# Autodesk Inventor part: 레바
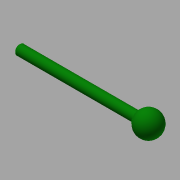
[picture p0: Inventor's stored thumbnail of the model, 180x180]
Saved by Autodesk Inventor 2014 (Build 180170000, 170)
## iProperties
Created: 2015-12
Part Number: 레바
Material: 스테인리스강
Document SubType Name: Modeling
Designer: mduedu
Density: 8.08 g/cm^3
Mass: 30.7693 g
Surface Area: 20.8622 cm^2
Volume: 3.80808 cm^3
Appearance: 진녹색
Author: mduedu
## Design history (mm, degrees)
sketch "스케치1"
  geometry: C1 r 3 at (0, 0); 1 further point
  constraints: 1 centre point, 1 coincident
  dimensions: "d0" = 6 diameter of C1
extrude "돌출1" new body sketch "스케치1" distance "d1" = 80; taper "d2" = 0 deg
sketch "스케치2"
  geometry: L1 (7.5, 0)-(-6, 0); L2 (-6, 4.5)-(-6, 0); A1 r 7.5 centre (0, 0) between (7.5, 0) and (-6, 4.5); 2 further points
  constraints: 4 end point, 2 coincident, 2 point on circle, 1 centre point, 1 horizontal, 1 perpendicular, 1 point on line
  dimensions: "d3" = 15 diameter of A1; "d10" = 6 distance from line of L2 point (0, 0)
revolve "회전1" sketch "스케치2" stored, may be unused: angle "d4" = 90 deg
chamfer "모따기1" distance "d7" = 0.5; stored, may be unused: second distance "d8" = 2, angle "d9" = 45 deg
fillet "모깎기2" dims "d11" = 0.3
node "솔리드1"
